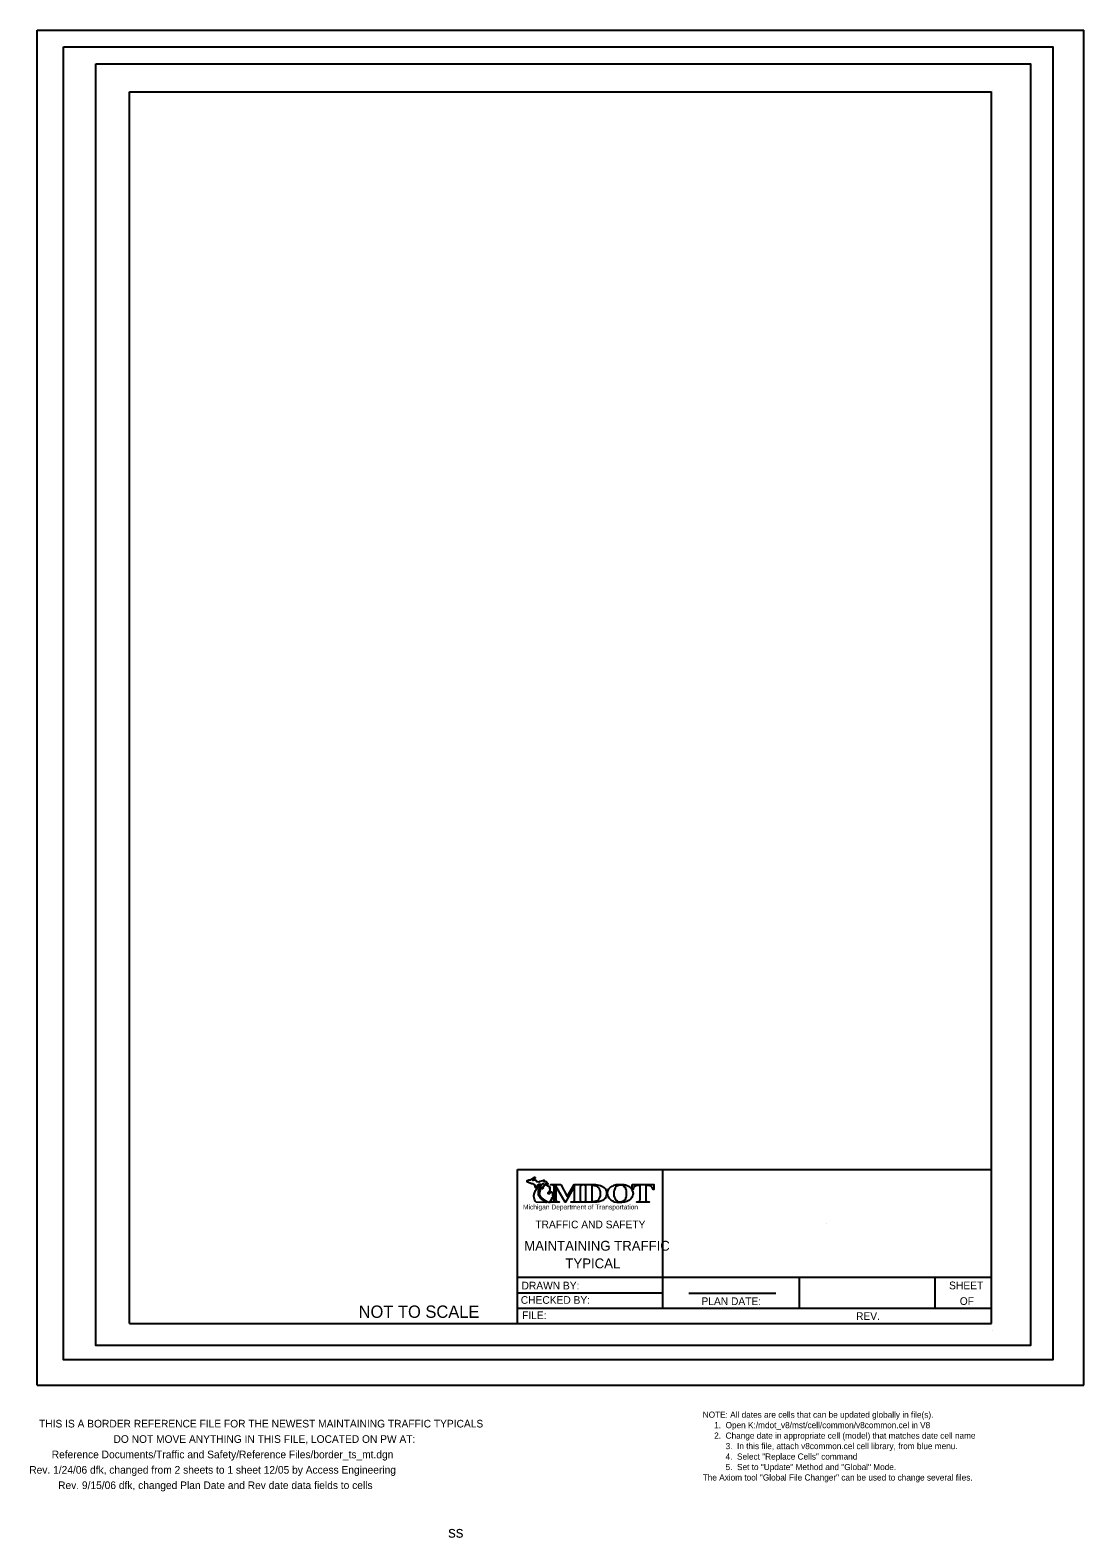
# Model space of a CAD drawing. Extents: x 16642 to 18318, y 7042 to 8266.
import ezdxf

# ---------------------------------------------------------------- set-up
doc = ezdxf.new("R2010")
doc.units = 0
for name, color, linetype in [('BORDER', 7, 'Continuous'), ('PRINT_SHAPES', 7, 'Continuous'), ('SCRATCH_LEVEL_A', 7, 'Continuous'), ('TRAFFIC_SIGNS_PR', 7, 'Continuous')]:
    doc.layers.add(name, color=color, linetype=linetype)

msp = doc.modelspace()

# ---------------------------------------------------------------- linework, layer by layer
at = {"layer": 'BORDER'}
for p, q in [((16647.8, 7166.2), (16647.8, 8266.2)), ((16647.8, 8266.2), (17497.8, 8266.2)), ((17497.8, 7166.2), (17497.8, 8266.2)), ((16669.3, 8252.7), (16669.3, 8252.7)), ((17472.5, 8252.7), (17472.5, 8252.7)), ((16695.5, 8217), (16695.5, 8217)), ((16722.8, 7216.2), (16722.8, 8216.2)), ((16722.8, 8216.2), (17422.8, 8216.2)), ((17422.8, 7216.2), (17422.8, 8216.2)), ((17423.5, 8217), (17423.5, 8217)), ((17037.8, 7216.2), (17037.8, 7341.2)), ((17037.8, 7341.2), (17422.8, 7341.2)), ((17155.8, 7228.8), (17155.8, 7341.2)), ((17155.8, 7341.2), (17155.8, 7341.2)), ((17289.2, 7297.5), (17289.2, 7297.5)), ((17037.8, 7253.8), (17422.8, 7253.8)), ((17267, 7228.8), (17267, 7253.8)), ((17377, 7228.8), (17377, 7253.8)), ((17037.8, 7241.2), (17155.8, 7241.2)), ((17177, 7240.8), (17247.7, 7240.8)), ((17037.8, 7228.8), (17422.8, 7228.8)), ((16695.5, 7210.7), (16695.5, 7210.7)), ((16722.8, 7216.2), (17422.8, 7216.2)), ((17423.5, 7210.7), (17423.5, 7210.7)), ((16669.3, 7198.7), (16669.3, 7198.7)), ((17472.5, 7198.7), (17472.5, 7198.7)), ((16647.8, 7166.2), (17497.8, 7166.2))]:
    msp.add_line(p, q, dxfattribs=at)
for points in [[(17045.2, 7331.9), (17045.4, 7331.9), (17045.4, 7331.7), (17045.9, 7331.2), (17049.6, 7330), (17049.9, 7329.6), (17050.1, 7330), (17050.8, 7329.5), (17051.2, 7329.4), (17051.3, 7329.3), (17051.4, 7329), (17052, 7328.9), (17052.1, 7327.9), (17052, 7327.6), (17052.5, 7327.7), (17052.3, 7326.7), (17052.6, 7326.5), (17054.3, 7329), (17054.5, 7328.6), (17055.6, 7329.3), (17055.2, 7328.7), (17055.4, 7328.5), (17056.2, 7329.4), (17056.7, 7329.5), (17057, 7329.2), (17057.9, 7329.5), (17058.4, 7330), (17059.9, 7329.5), (17060.2, 7329.1), (17060.5, 7329.2), (17060.3, 7329.5), (17060.6, 7329.8), (17061.1, 7329.7), (17062.8, 7329.6), (17062.8, 7329.8), (17062.4, 7329.9), (17062, 7330.5), (17061.8, 7330.5), (17061.8, 7331), (17061.4, 7331.3), (17060.8, 7331.2), (17060.6, 7331.4), (17060.3, 7331.2), (17059.6, 7331.2), (17059.8, 7332.3), (17059.1, 7332.4), (17058.6, 7332), (17055.7, 7331.6), (17055.4, 7331), (17054.5, 7331.4), (17053.5, 7331.3), (17052.5, 7332.7), (17051.7, 7332.7), (17051.1, 7332.7), (17051.3, 7333), (17051, 7332.9), (17050.6, 7332.3), (17050.4, 7332.3), (17050.6, 7332.9), (17051.2, 7333.9), (17052.1, 7334.5), (17052.5, 7334.5), (17052.3, 7334.9), (17051.6, 7334.9), (17049.6, 7333.6), (17048.9, 7333.3), (17048.5, 7332.7), (17047, 7332.7)], [(17053, 7314.7), (17052.5, 7315.4), (17052, 7316.4), (17051.8, 7317.3), (17051.3, 7319.3), (17051.3, 7320.2), (17051.8, 7322.2), (17052.5, 7324.2), (17053, 7325.1), (17053.8, 7325.9), (17054.5, 7327), (17055.3, 7327.7), (17057.5, 7329), (17056.8, 7328.1), (17056.2, 7327.5), (17056, 7326.8), (17055.3, 7325.9), (17055.2, 7325.1), (17054.8, 7324.2), (17054.7, 7323.1), (17054.7, 7322), (17054.8, 7321.1), (17055.3, 7319.8), (17056, 7318.9), (17056.8, 7317.8), (17058, 7316.7), (17059.5, 7315.6), (17061.3, 7314.6)], [(17064.3, 7314.7), (17064.3, 7315.3), (17064.7, 7315.8), (17064.9, 7315.7), (17065.2, 7316.4), (17065.2, 7317.1), (17065.7, 7317.1), (17065.7, 7317.5), (17065.9, 7317.8), (17065.9, 7318.2), (17066.3, 7318.3), (17066.5, 7317.8), (17066.8, 7318.3), (17066.8, 7319.3), (17067, 7319.3), (17067, 7319.5), (17066.7, 7320.2), (17066.7, 7321.1), (17066.5, 7321.5), (17066.5, 7322.4), (17065.9, 7322.6), (17065.7, 7322.9), (17065.4, 7323.1), (17064.8, 7322.7), (17064.2, 7322.6), (17064.3, 7322.5), (17064.3, 7322.4), (17063.9, 7322), (17063.8, 7322), (17063.9, 7321.5), (17063.4, 7321.5), (17062.9, 7321.7), (17062.7, 7321.9), (17062.8, 7322.7), (17063.4, 7322.7), (17063.6, 7322.9), (17063.6, 7323.3), (17063.8, 7323.6), (17063.9, 7323.9), (17064.1, 7323.9), (17064.3, 7324.2), (17064.3, 7325.9), (17064, 7326.1), (17064, 7326.6), (17064.3, 7326.4), (17064.1, 7327.3), (17062.9, 7327.7), (17061.7, 7328.6), (17061.3, 7328.6), (17060.9, 7328.7), (17060.5, 7329), (17059.7, 7329), (17059.6, 7328.8), (17059.6, 7328.4), (17059.4, 7328.1), (17059.5, 7327.7), (17059.2, 7327.7), (17059.1, 7327.5), (17058.9, 7327.5), (17058.6, 7327.3), (17058.7, 7326.2), (17058.1, 7325.5), (17058.4, 7326.1), (17058.3, 7326.1), (17057.9, 7325.7), (17058, 7327), (17057.7, 7326.6), (17057.5, 7326.1), (17057.3, 7326.2), (17056.9, 7326.1), (17056.6, 7325.9), (17056.5, 7325.3), (17056.2, 7325.1), (17056.4, 7324.9), (17056, 7323.3), (17055.5, 7323.1), (17055.7, 7322.7), (17055.8, 7322.1), (17055.5, 7321.7), (17055.5, 7321), (17056.2, 7319.8), (17056.7, 7319.3), (17057, 7318.6), (17059, 7317), (17061.6, 7315.3), (17063.4, 7314.7)], [(17073.2, 7329.1), (17078.3, 7319.5), (17083.8, 7329.1), (17091.5, 7329.1), (17091.5, 7328.8), (17091, 7328.8), (17089.5, 7328.4), (17089.3, 7328.4), (17089.3, 7328.3), (17089, 7327.9), (17088.8, 7327.5), (17088.8, 7316.1), (17089, 7315.8), (17089.5, 7315.3), (17090.3, 7315.1), (17091.5, 7315.1), (17091.5, 7314.7), (17081.5, 7314.7), (17081.5, 7315.1), (17083, 7315.1), (17083.5, 7315.3), (17083.8, 7315.6), (17084.2, 7315.8), (17084.2, 7316.1), (17084.2, 7327.7), (17076.8, 7314.7), (17076.5, 7314.7), (17069, 7327.7), (17069, 7316.7), (17069.2, 7315.8), (17069.8, 7315.4), (17070.5, 7315.1), (17071.7, 7315.1), (17071.7, 7314.7), (17065, 7314.7), (17065, 7315.1), (17065.2, 7315.1), (17066.5, 7315.3), (17067, 7315.4), (17067.2, 7315.6), (17067.7, 7316), (17067.8, 7316.4), (17067.8, 7327.5), (17067.7, 7327.9), (17067.5, 7328.3), (17067, 7328.4), (17066.5, 7328.6), (17065.7, 7328.8), (17065, 7328.8), (17065, 7329.1)], [(17101.2, 7328.1), (17100.2, 7328.1), (17098.2, 7328.3), (17098.2, 7316.1), (17098.3, 7316), (17098.8, 7315.6), (17099.8, 7315.4), (17100.8, 7315.6), (17101.7, 7315.8), (17101.7, 7314.7), (17090.8, 7314.7), (17090.8, 7315.1), (17092.2, 7315.1), (17092.7, 7315.3), (17093.2, 7315.6), (17093.3, 7315.8), (17093.5, 7316.1), (17093.5, 7327.5), (17093.3, 7327.9), (17093.2, 7328.3), (17091.5, 7328.8), (17090.8, 7328.8), (17090.8, 7329.1), (17101.2, 7329.1), (17101.7, 7329), (17101.7, 7327.9)], [(17102, 7315.8), (17102.8, 7316), (17103.8, 7317.1), (17104.2, 7317.6), (17104.5, 7318.2), (17104.8, 7318.7), (17105.2, 7320), (17105.2, 7321.7), (17105.2, 7322.9), (17105, 7324.2), (17104.5, 7325.3), (17104, 7326.1), (17103.5, 7326.8), (17103, 7327.3), (17102.3, 7327.7), (17101.7, 7327.9), (17101.7, 7329), (17102.5, 7329), (17104, 7328.6), (17105.2, 7328.4), (17106.3, 7327.9), (17108.2, 7326.6), (17109, 7325.9), (17109.5, 7324.8), (17110, 7324), (17110.2, 7323.5), (17110.2, 7322.7), (17110.3, 7321.9), (17110.3, 7321.1), (17110, 7319.7), (17109.7, 7319.1), (17109, 7317.8), (17108.5, 7317.5), (17108, 7316.9), (17107, 7316.1), (17105.7, 7315.6), (17104, 7315.1), (17102.2, 7314.7), (17101.7, 7314.7), (17101.7, 7315.8)], [(17121.3, 7328.6), (17120.2, 7328.4), (17119, 7328.1), (17118.5, 7327.7), (17118, 7327.5), (17117.2, 7326.4), (17116.8, 7325.7), (17116.5, 7324.4), (17116.2, 7323.3), (17116.2, 7320), (17116.7, 7318.6), (17117.2, 7317.5), (17118, 7316.4), (17118.7, 7315.8), (17119.3, 7315.4), (17121.2, 7315.1), (17121.3, 7315.1), (17121.3, 7314.6), (17118.8, 7314.6), (17116.7, 7314.9), (17115.8, 7315.4), (17114.8, 7315.8), (17114, 7316.4), (17113.3, 7316.9), (17112.2, 7318), (17111.5, 7319.3), (17111.2, 7320.5), (17111, 7321.9), (17111, 7322.6), (17111.2, 7323.5), (17111.3, 7324.2), (17112, 7325.5), (17113.2, 7326.8), (17114.7, 7327.7), (17115.5, 7328.1), (17116.2, 7328.6), (17117.2, 7328.8), (17118, 7329.1), (17119, 7329.1), (17121.3, 7329.1)], [(17122.7, 7315.3), (17123.8, 7315.6), (17125.5, 7317.1), (17125.8, 7317.8), (17126, 7318.7), (17126.3, 7319.5), (17126.3, 7324.2), (17126, 7325.1), (17125.8, 7325.9), (17125.5, 7326.6), (17124.8, 7327.1), (17124.5, 7327.7), (17123.3, 7328.3), (17122, 7328.6), (17121.3, 7328.6), (17121.3, 7329.1), (17123.3, 7329.1), (17124.3, 7329.1), (17125.5, 7328.8), (17126.3, 7328.6), (17127, 7328.3), (17128, 7327.7), (17129.5, 7326.8), (17130.5, 7325.5), (17131, 7324.8), (17131, 7324.2), (17131.5, 7323.5), (17131.5, 7322.6), (17131.7, 7321.9), (17131.5, 7320.5), (17131, 7319.3), (17130.7, 7318.7), (17130.3, 7318.2), (17130, 7317.6), (17128.8, 7316.4), (17126.8, 7315.4), (17126, 7315.1), (17124.8, 7314.7), (17122.7, 7314.6), (17121.3, 7314.6), (17121.3, 7315.1)], [(17131, 7329.1), (17148.5, 7329.1), (17148.5, 7325.1), (17148, 7325.1), (17147.8, 7325.9), (17147.5, 7326.2), (17147.2, 7326.8), (17147, 7327.1), (17146.2, 7327.7), (17145.3, 7328.1), (17144.7, 7328.3), (17142, 7328.3), (17142, 7317.3), (17142.2, 7316.1), (17142.2, 7315.8), (17142.5, 7315.6), (17143, 7315.3), (17143.5, 7315.1), (17144.8, 7315.1), (17144.8, 7314.7), (17134.8, 7314.7), (17134.8, 7315.1), (17136, 7315.1), (17136.8, 7315.3), (17137, 7315.6), (17137.2, 7315.8), (17137.2, 7316.1), (17137.5, 7317.3), (17137.5, 7328.3), (17135, 7328.3), (17133.7, 7327.9), (17133.2, 7327.7), (17132.5, 7327.1), (17132.2, 7326.6), (17131.8, 7325.9), (17131.7, 7325.1), (17131, 7325.1)]]:
    msp.add_lwpolyline(points, close=True, dxfattribs=at)
at = {"layer": 'PRINT_SHAPES'}
for points in [[(16669.3, 8252.7), (17472.5, 8252.7), (17472.5, 7186.8), (16669.3, 7186.8)], [(16695.5, 8239), (17454.4, 8239), (17454.4, 7198.4), (16695.5, 7198.4)]]:
    msp.add_lwpolyline(points, close=True, dxfattribs=at)

# ---------------------------------------------------------------- texts
at = {"layer": 'BORDER'}
for s, height, p in [('Michigan Department of Transportation', 3.9, (17042.4, 7308.9)), ('TRAFFIC AND SAFETY', 6.2, (17052.4, 7293.6)), ('MAINTAINING TRAFFIC', 8, (17043.3, 7275.4)), ('TYPICAL', 8, (17076.8, 7261.1)), ('DRAWN BY:', 6.2, (17041.2, 7244)), ('SHEET', 6.25, (17388.3, 7244.1)), ('CHECKED BY:', 6.2, (17040.6, 7232.3)), ('PLAN DATE:', 6.2, (17187.3, 7231.3)), ('OF', 6.2, (17397, 7231.4)), ('NOT TO SCALE', 10, (16908.9, 7220.9)), ('FILE:', 6.2, (17041.6, 7219.9)), ('REV.', 6.2, (17312.8, 7219.2)), ('NOTE: All dates are cells that can be updated globally in file(s).', 5, (17188.3, 7139.8)), ('     1.  Open K:/mdot_v8/mst/cell/common/v8common.cel in V8', 5, (17188.3, 7131.3)), ('     2.  Change date in appropriate cell (model) that matches date cell name', 5, (17188.3, 7122.8)), ('          3.  In this file, attach v8common.cel cell library, from blue menu.', 5, (17188.3, 7114.3)), ('          4.  Select "Replace Cells" command', 5, (17188.3, 7105.8)), ('          5.  Set to "Update" Method and "Global" Mode.', 5, (17188.3, 7097.3)), ('The Axiom tool "Global File Changer" can be used to change several files.', 5, (17188.3, 7088.8))]:
    msp.add_text(s, height=height, dxfattribs=at).set_placement(p)
at = {"layer": 'SCRATCH_LEVEL_A'}
for s, p in [('THIS IS A BORDER REFERENCE FILE FOR THE NEWEST MAINTAINING TRAFFIC TYPICALS', (16649.4, 7131.9)), ('DO NOT MOVE ANYTHING IN THIS FILE, LOCATED ON PW AT:', (16709.9, 7119.4)), ('Reference Documents/Traffic and Safety/Reference Files/border_ts_mt.dgn', (16659.7, 7106.9)), ('Rev. 1/24/06 dfk, changed from 2 sheets to 1 sheet 12/05 by Access Engineering', (16641.5, 7094.4)), ('Rev. 9/15/06 dfk, changed Plan Date and Rev date data fields to cells', (16664.9, 7081.9))]:
    msp.add_text(s, height=6.2, dxfattribs=at).set_placement(p)
at = {"layer": 'TRAFFIC_SIGNS_PR'}
msp.add_text('ss', height=9.3, dxfattribs=at).set_placement((16981.6, 7042.4))

doc.saveas('drawing.dxf')
